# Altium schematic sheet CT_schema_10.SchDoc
size 519 x 434 mm
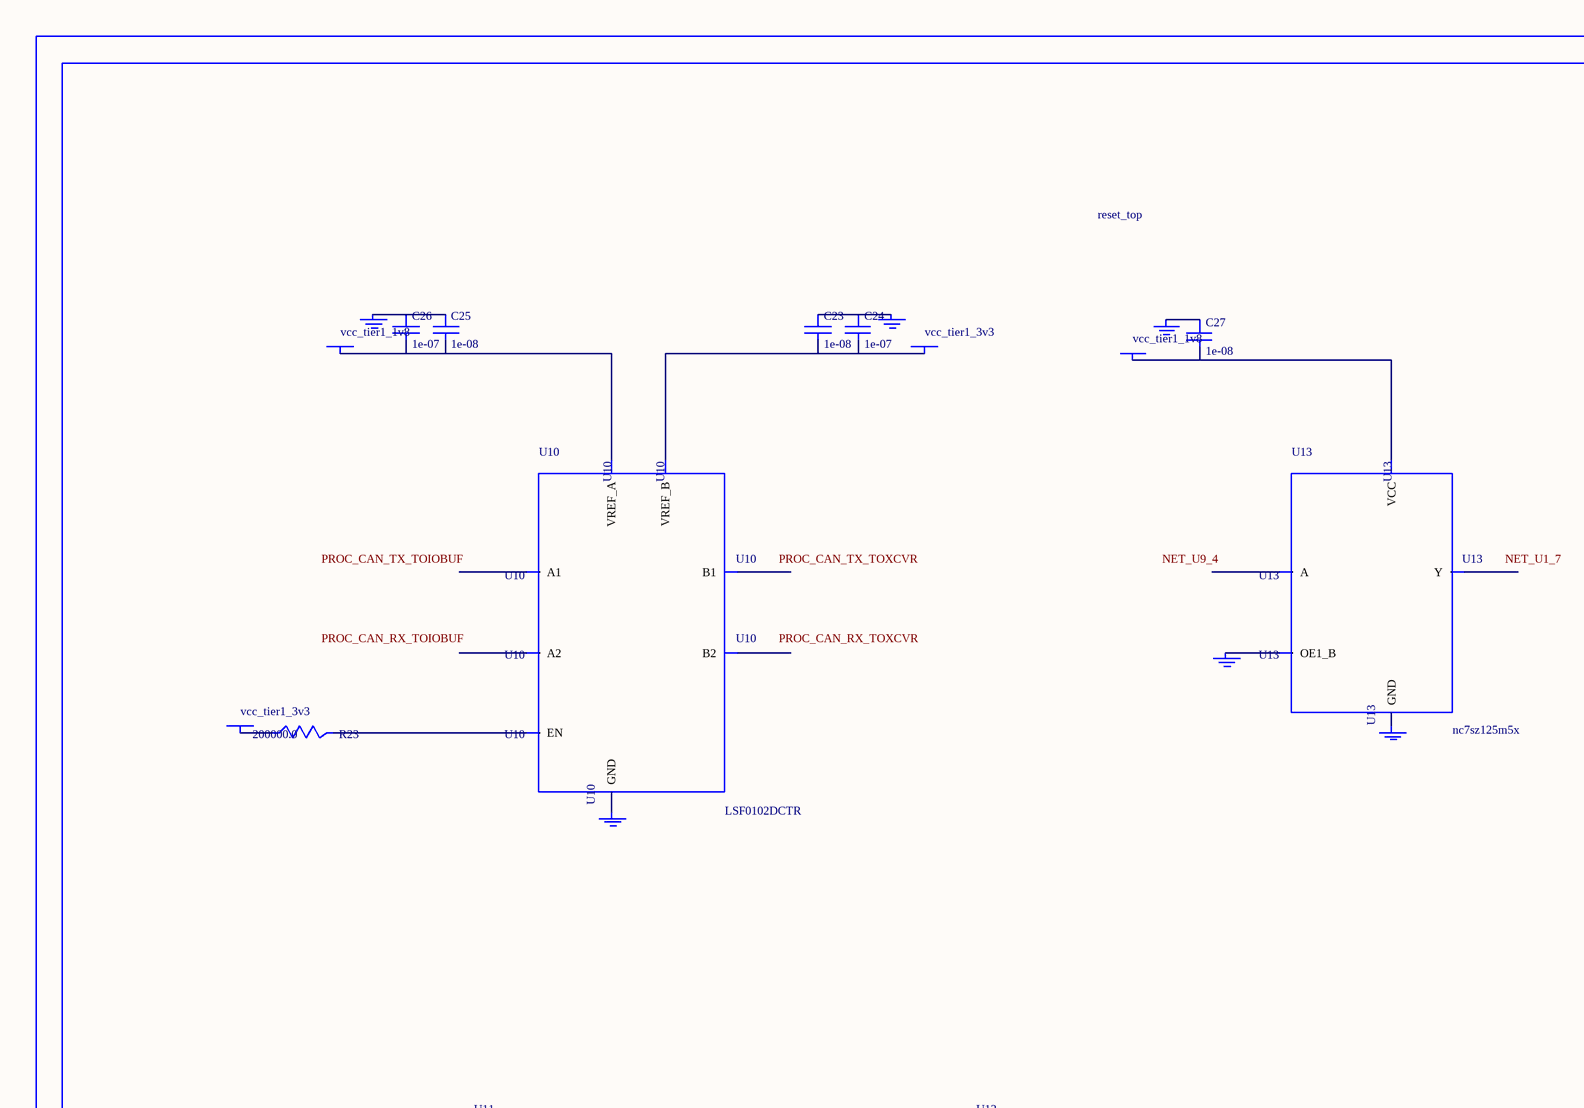
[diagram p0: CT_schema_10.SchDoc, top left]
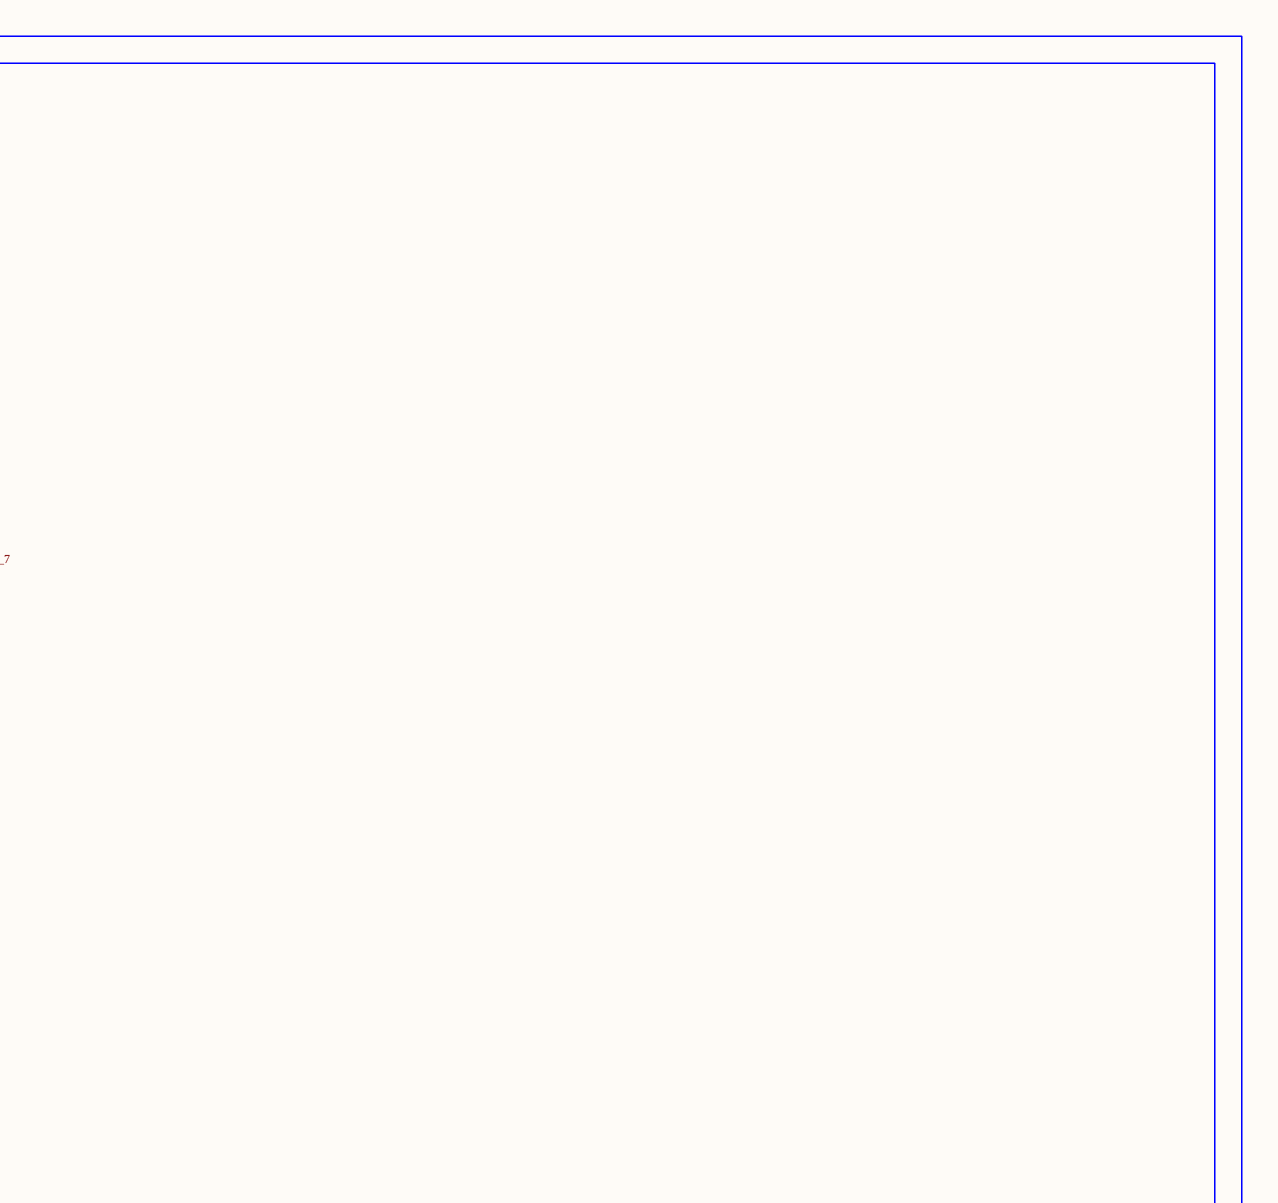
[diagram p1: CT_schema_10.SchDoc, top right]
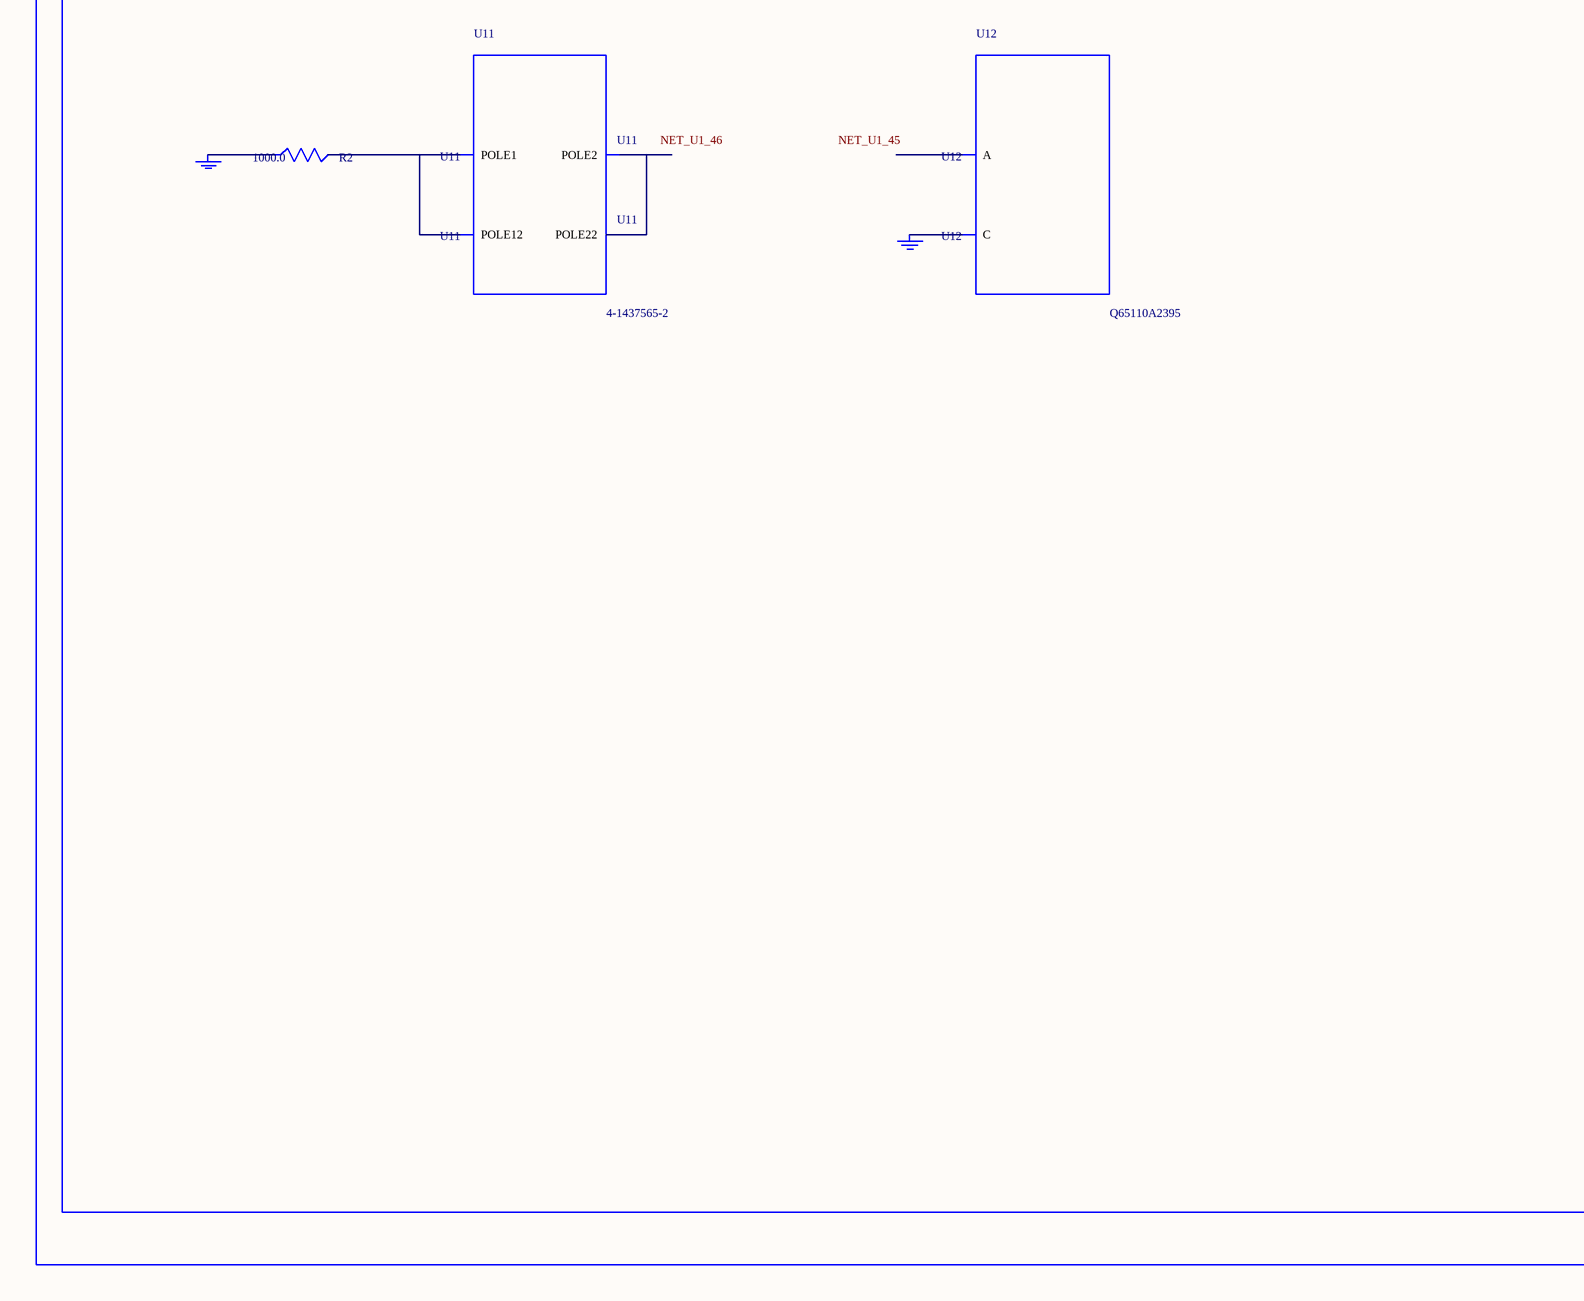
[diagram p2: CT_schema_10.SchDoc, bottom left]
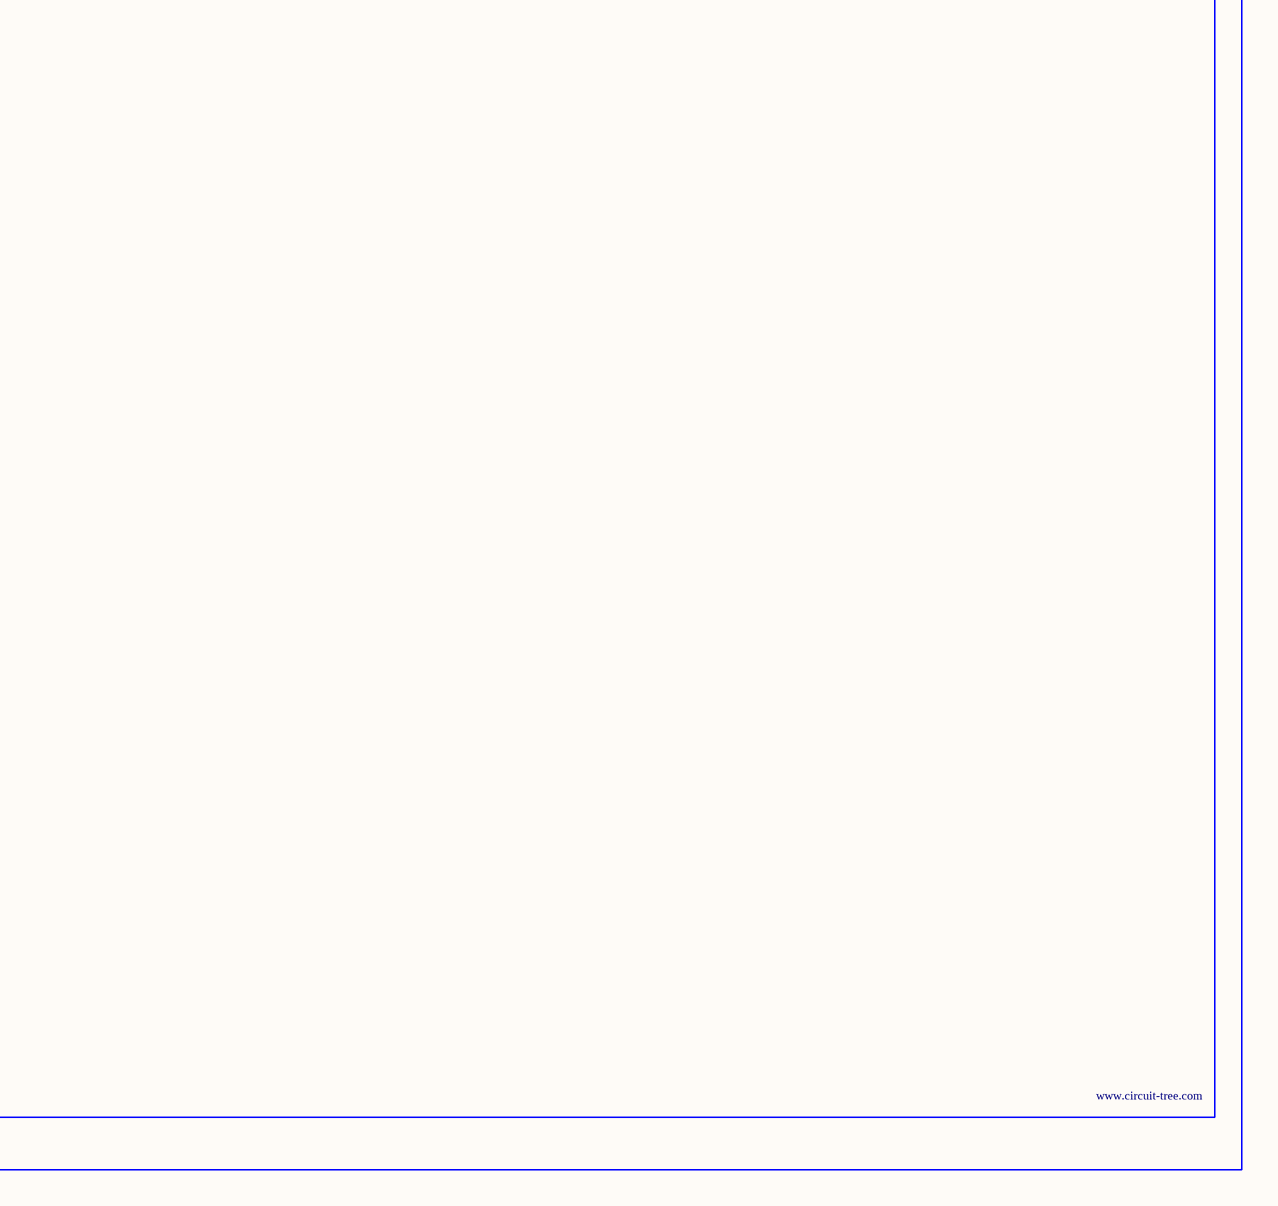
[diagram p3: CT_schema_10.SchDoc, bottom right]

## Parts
BORDER9  (no value)
C23  1e-08  [C0402]
C24  1e-07  [C0402]
C25  1e-08  [C0402]
C26  1e-07  [C0402]
C27  1e-08  [C0402]
GND_INSTANCE_9_0  (no value)
GND_INSTANCE_9_1  (no value)
GND_INSTANCE_9_2  (no value)
GND_INSTANCE_9_3  (no value)
GND_INSTANCE_9_4  (no value)
GND_INSTANCE_9_5  (no value)
GND_INSTANCE_9_6  (no value)
GND_INSTANCE_9_7  (no value)
POWER_INSTANCE_9_0  vcc_tier1_1v8
POWER_INSTANCE_9_1  vcc_tier1_3v3
POWER_INSTANCE_9_2  vcc_tier1_3v3
POWER_INSTANCE_9_3  vcc_tier1_1v8
R2  1000.0  [R0603]
R23  200000.0  [R0603]
U10  LSF0102DCTR  [DCU0008A_N]
U11  4-1437565-2  [SW_4-1437565-2]
U12  Q65110A2395  [LGM67K-G1J2-24-Z]
U13  nc7sz125m5x  [NC7SZ125M5X]

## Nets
NetC23_1: C23.1 C24.1 GND_INSTANCE_9_1.0(GND)
NetC23_2: C23.2 C24.2 POWER_INSTANCE_9_1.0(PWR) U10.7(VREF_B)
NetC25_1: C25.1 C26.1 GND_INSTANCE_9_0.0(GND)
NetC25_2: C25.2 C26.2 POWER_INSTANCE_9_0.0(PWR) U10.2(VREF_A)
NetC27_1: C27.1 GND_INSTANCE_9_5.0(GND)
NetC27_2: C27.2 POWER_INSTANCE_9_3.0(PWR) U13.5(VCC)
NetGND_INSTANCE_9_2_0: GND_INSTANCE_9_2.0(GND) U10.1(GND)
NetGND_INSTANCE_9_3_0: GND_INSTANCE_9_3.0(GND) R2.1
NetGND_INSTANCE_9_4_0: GND_INSTANCE_9_4.0(GND) U12.C
NetGND_INSTANCE_9_6_0: GND_INSTANCE_9_6.0(GND) U13.1(OE1_B)
NetGND_INSTANCE_9_7_0: GND_INSTANCE_9_7.0(GND) U13.3(GND)
NetPOWER_INSTANCE_9_2_0: POWER_INSTANCE_9_2.0(PWR) R23.1
NetR2_2: R2.2 U11.1(POLE1) U11.2(POLE12)
NetR23_2: R23.2 U10.8(EN)
NetU11_3: U11.3(POLE2) U11.4(POLE22)

Not connected (* = marked no-connect by the designer): U10 3(A1) 4(A2) 5(B2) 6(B1); U12 A; U13 2(A) 4(Y)

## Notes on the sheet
- Labels drawn without touching a wire or pin: NET_U1_7, NET_U1_45, NET_U1_46, NET_U9_4, PROC_CAN_RX_TOIOBUF, PROC_CAN_RX_TOXCVR, PROC_CAN_TX_TOIOBUF, PROC_CAN_TX_TOXCVR

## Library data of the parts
BORDER9 = BORDER_PAGE9
C23 C25 C27 = C0402C103K3RAC
C24 C26 = C0402C104K3RACTU
GND_INSTANCE_9_0-GND_INSTANCE_9_7 = GND
POWER_INSTANCE_9_0-POWER_INSTANCE_9_3 = PWR
R2 = RC0603JR-071KL
R23 = RC0603JR-07200KL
